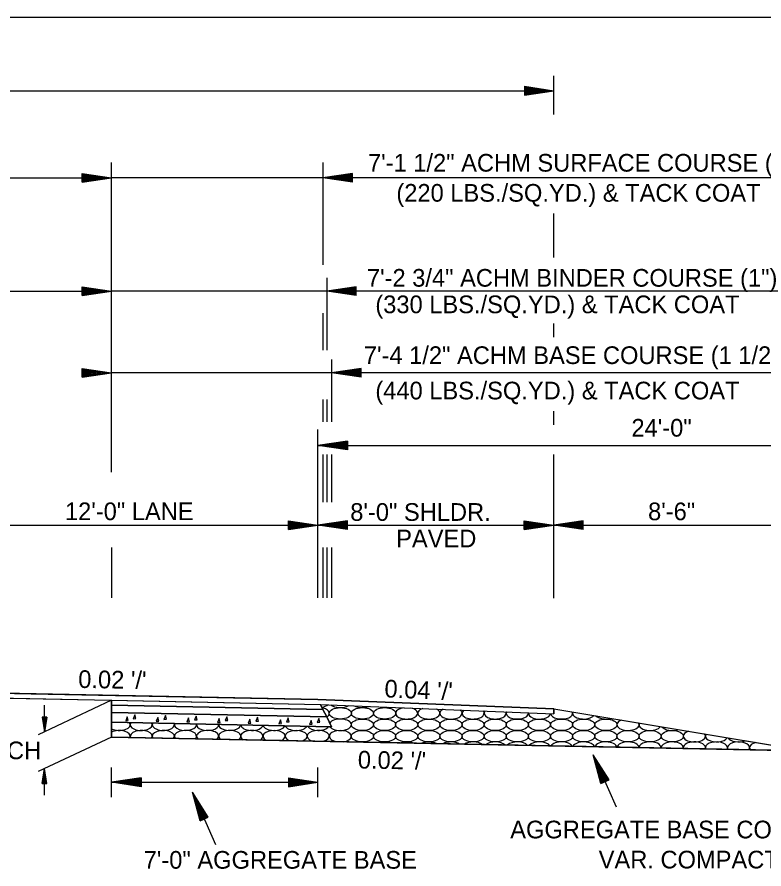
# Model space of a CAD drawing. Extents: x 1371763 to 1372860, y 385599 to 385872.
# Drawn here: x 1372091.19 to 1372116.52, y 385642.37 to 385671.28 of the extents above; entities that cross this region are included whole.
import ezdxf

# ---------------------------------------------------------------- set-up
doc = ezdxf.new("R2010")
doc.units = 0
doc.layers.add('R_Draft', color=7, linetype='Continuous')

msp = doc.modelspace()

# ---------------------------------------------------------------- linework, layer by layer
at = {"layer": 'R_Draft'}
for p, q in [((1372048.826, 385671.277), (1372117.962, 385671.277)), ((1372109.391, 385667.967), (1372109.391, 385669.287)), ((1372057.39, 385668.777), (1372109.391, 385668.777)), ((1372108.391, 385668.927), (1372109.391, 385668.777)), ((1372108.391, 385668.927), (1372108.391, 385668.627)), ((1372108.391, 385668.902), (1372109.224, 385668.777)), ((1372108.391, 385668.876), (1372109.052, 385668.777)), ((1372108.391, 385668.851), (1372108.885, 385668.777)), ((1372108.391, 385668.825), (1372108.716, 385668.777)), ((1372108.391, 385668.8), (1372108.549, 385668.777)), ((1372108.391, 385668.627), (1372109.391, 385668.777)), ((1372108.391, 385668.728), (1372108.716, 385668.777)), ((1372108.391, 385668.677), (1372109.052, 385668.777)), ((1372108.391, 385668.652), (1372109.224, 385668.777)), ((1372108.391, 385668.702), (1372108.885, 385668.777)), ((1372108.391, 385668.753), (1372108.549, 385668.777)), ((1372094.392, 385655.834), (1372094.393, 385666.343)), ((1372101.562, 385666.343), (1372101.562, 385662.864)), ((1372093.393, 385665.971), (1372094.393, 385665.821)), ((1372093.393, 385665.671), (1372093.393, 385665.971)), ((1372093.393, 385665.946), (1372094.226, 385665.821)), ((1372093.393, 385665.921), (1372094.054, 385665.821)), ((1372093.393, 385665.896), (1372093.888, 385665.821)), ((1372093.393, 385665.87), (1372093.718, 385665.821)), ((1372102.562, 385665.971), (1372101.562, 385665.821)), ((1372102.562, 385665.946), (1372101.729, 385665.821)), ((1372102.562, 385665.921), (1372101.901, 385665.821)), ((1372102.562, 385665.896), (1372102.067, 385665.821)), ((1372102.562, 385665.87), (1372102.237, 385665.821)), ((1372102.562, 385665.671), (1372102.562, 385665.971)), ((1372072.393, 385665.821), (1372094.393, 385665.821)), ((1372093.393, 385665.845), (1372093.551, 385665.821)), ((1372093.393, 385665.671), (1372094.393, 385665.821)), ((1372093.393, 385665.773), (1372093.718, 385665.821)), ((1372093.393, 385665.722), (1372094.054, 385665.821)), ((1372093.393, 385665.696), (1372094.226, 385665.821)), ((1372093.393, 385665.747), (1372093.888, 385665.821)), ((1372093.393, 385665.798), (1372093.551, 385665.821)), ((1372120.069, 385665.821), (1372094.393, 385665.821)), ((1372102.562, 385665.671), (1372101.562, 385665.821)), ((1372102.562, 385665.696), (1372101.729, 385665.821)), ((1372102.562, 385665.722), (1372101.901, 385665.821)), ((1372102.562, 385665.747), (1372102.067, 385665.821)), ((1372102.562, 385665.773), (1372102.237, 385665.821)), ((1372102.562, 385665.845), (1372102.404, 385665.821)), ((1372102.562, 385665.798), (1372102.404, 385665.821)), ((1372109.391, 385663.113), (1372109.391, 385664.613)), ((1372101.688, 385662.427), (1372101.688, 385659.975)), ((1372093.393, 385662.127), (1372094.393, 385661.977)), ((1372093.393, 385661.827), (1372093.393, 385662.127)), ((1372102.688, 385662.127), (1372101.688, 385661.977)), ((1372102.688, 385661.827), (1372102.688, 385662.127)), ((1372072.393, 385661.977), (1372094.393, 385661.977)), ((1372093.393, 385662.102), (1372094.226, 385661.977)), ((1372093.393, 385662.076), (1372094.054, 385661.977)), ((1372093.393, 385662.051), (1372093.888, 385661.977)), ((1372093.393, 385662.026), (1372093.718, 385661.977)), ((1372093.393, 385662), (1372093.551, 385661.977)), ((1372093.393, 385661.827), (1372094.393, 385661.977)), ((1372093.393, 385661.928), (1372093.718, 385661.977)), ((1372093.393, 385661.877), (1372094.054, 385661.977)), ((1372093.393, 385661.852), (1372094.226, 385661.977)), ((1372093.393, 385661.902), (1372093.888, 385661.977)), ((1372093.393, 385661.953), (1372093.551, 385661.977)), ((1372119.435, 385661.977), (1372094.393, 385661.977)), ((1372102.688, 385661.827), (1372101.688, 385661.977)), ((1372102.688, 385662.102), (1372101.855, 385661.977)), ((1372102.688, 385661.852), (1372101.855, 385661.977)), ((1372102.688, 385662.077), (1372102.027, 385661.977)), ((1372102.688, 385661.878), (1372102.027, 385661.977)), ((1372102.688, 385662.052), (1372102.193, 385661.977)), ((1372102.688, 385661.903), (1372102.193, 385661.977)), ((1372102.688, 385662.026), (1372102.363, 385661.977)), ((1372102.688, 385661.929), (1372102.363, 385661.977)), ((1372102.688, 385662.001), (1372102.53, 385661.977)), ((1372102.688, 385661.954), (1372102.53, 385661.977)), ((1372101.562, 385661.227), (1372101.562, 385659.975)), ((1372109.391, 385660.416), (1372109.391, 385660.881)), ((1372101.856, 385659.652), (1372101.856, 385657.536)), ((1372093.392, 385659.352), (1372094.392, 385659.202)), ((1372093.392, 385659.052), (1372093.392, 385659.352)), ((1372093.392, 385659.327), (1372094.225, 385659.202)), ((1372093.392, 385659.301), (1372094.053, 385659.202)), ((1372093.392, 385659.276), (1372093.887, 385659.202)), ((1372093.392, 385659.251), (1372093.717, 385659.202)), ((1372093.392, 385659.225), (1372093.55, 385659.202)), ((1372102.856, 385659.352), (1372101.856, 385659.202)), ((1372102.856, 385659.327), (1372102.023, 385659.202)), ((1372102.856, 385659.301), (1372102.195, 385659.202)), ((1372102.856, 385659.276), (1372102.362, 385659.202)), ((1372102.856, 385659.251), (1372102.531, 385659.202)), ((1372102.856, 385659.225), (1372102.698, 385659.202)), ((1372102.856, 385659.052), (1372102.856, 385659.352)), ((1372093.392, 385659.052), (1372094.392, 385659.202)), ((1372093.392, 385659.153), (1372093.717, 385659.202)), ((1372093.392, 385659.102), (1372094.053, 385659.202)), ((1372093.392, 385659.077), (1372094.225, 385659.202)), ((1372093.392, 385659.127), (1372093.887, 385659.202)), ((1372093.392, 385659.178), (1372093.55, 385659.202)), ((1372119.435, 385659.202), (1372094.393, 385659.202)), ((1372102.856, 385659.052), (1372101.856, 385659.202)), ((1372102.856, 385659.077), (1372102.023, 385659.202)), ((1372102.856, 385659.102), (1372102.195, 385659.202)), ((1372102.856, 385659.127), (1372102.362, 385659.202)), ((1372102.856, 385659.153), (1372102.531, 385659.202)), ((1372102.856, 385659.178), (1372102.698, 385659.202)), ((1372101.562, 385658.301), (1372101.562, 385657.536)), ((1372101.688, 385658.301), (1372101.688, 385657.536)), ((1372109.391, 385657.442), (1372109.391, 385657.908)), ((1372101.39, 385651.566), (1372101.391, 385657.279)), ((1372102.391, 385656.889), (1372101.391, 385656.739)), ((1372101.391, 385656.739), (1372125.391, 385656.739)), ((1372102.391, 385656.589), (1372101.391, 385656.739)), ((1372102.391, 385656.864), (1372101.558, 385656.739)), ((1372102.391, 385656.614), (1372101.558, 385656.739)), ((1372102.391, 385656.838), (1372101.73, 385656.739)), ((1372102.391, 385656.639), (1372101.73, 385656.739)), ((1372102.391, 385656.813), (1372101.896, 385656.739)), ((1372102.391, 385656.664), (1372101.896, 385656.739)), ((1372102.391, 385656.787), (1372102.066, 385656.739)), ((1372102.391, 385656.69), (1372102.066, 385656.739)), ((1372102.391, 385656.762), (1372102.233, 385656.739)), ((1372102.391, 385656.715), (1372102.233, 385656.739)), ((1372102.391, 385656.889), (1372102.391, 385656.589)), ((1372101.562, 385656.428), (1372101.562, 385654.819)), ((1372101.688, 385656.428), (1372101.688, 385654.819)), ((1372101.856, 385656.428), (1372101.856, 385654.819)), ((1372109.39, 385651.56), (1372109.391, 385656.427)), ((1372089.39, 385654.032), (1372101.39, 385654.032)), ((1372100.39, 385654.182), (1372101.39, 385654.032)), ((1372100.39, 385653.882), (1372100.39, 385654.182)), ((1372100.39, 385654.157), (1372101.223, 385654.032)), ((1372100.39, 385654.132), (1372101.051, 385654.032)), ((1372100.39, 385654.107), (1372100.885, 385654.032)), ((1372100.39, 385654.081), (1372100.715, 385654.032)), ((1372100.39, 385654.056), (1372100.548, 385654.032)), ((1372100.39, 385653.882), (1372101.39, 385654.032)), ((1372100.39, 385653.984), (1372100.715, 385654.032)), ((1372100.39, 385653.933), (1372101.051, 385654.032)), ((1372100.39, 385653.907), (1372101.223, 385654.032)), ((1372100.39, 385653.958), (1372100.885, 385654.032)), ((1372100.39, 385654.009), (1372100.548, 385654.032)), ((1372102.39, 385654.182), (1372101.39, 385654.032)), ((1372102.39, 385653.882), (1372101.39, 385654.032)), ((1372101.39, 385654.032), (1372109.39, 385654.032)), ((1372102.39, 385654.157), (1372101.557, 385654.032)), ((1372102.39, 385653.907), (1372101.557, 385654.032)), ((1372102.39, 385654.132), (1372101.729, 385654.032)), ((1372102.39, 385653.933), (1372101.729, 385654.032)), ((1372102.39, 385654.107), (1372101.896, 385654.032)), ((1372102.39, 385653.958), (1372101.896, 385654.032)), ((1372102.39, 385654.081), (1372102.065, 385654.032)), ((1372102.39, 385653.984), (1372102.065, 385654.032)), ((1372102.39, 385654.056), (1372102.232, 385654.032)), ((1372102.39, 385654.009), (1372102.232, 385654.032)), ((1372102.39, 385653.882), (1372102.39, 385654.182)), ((1372108.39, 385654.182), (1372109.39, 385654.032)), ((1372108.39, 385653.882), (1372108.39, 385654.182)), ((1372108.39, 385654.157), (1372109.223, 385654.032)), ((1372108.39, 385654.132), (1372109.051, 385654.032)), ((1372108.39, 385654.107), (1372108.885, 385654.032)), ((1372108.39, 385654.081), (1372108.715, 385654.032)), ((1372108.39, 385654.056), (1372108.548, 385654.032)), ((1372108.39, 385653.882), (1372109.39, 385654.032)), ((1372108.39, 385653.984), (1372108.715, 385654.032)), ((1372108.39, 385653.933), (1372109.051, 385654.032)), ((1372108.39, 385653.907), (1372109.223, 385654.032)), ((1372108.39, 385653.958), (1372108.885, 385654.032)), ((1372108.39, 385654.009), (1372108.548, 385654.032)), ((1372110.39, 385654.182), (1372109.39, 385654.032)), ((1372110.39, 385653.882), (1372109.39, 385654.032)), ((1372109.39, 385654.032), (1372117.962, 385654.031)), ((1372110.39, 385654.157), (1372109.557, 385654.032)), ((1372110.39, 385653.907), (1372109.557, 385654.032)), ((1372110.39, 385654.132), (1372109.729, 385654.032)), ((1372110.39, 385653.933), (1372109.729, 385654.032)), ((1372110.39, 385654.107), (1372109.896, 385654.032)), ((1372110.39, 385653.958), (1372109.896, 385654.032)), ((1372110.39, 385654.081), (1372110.065, 385654.032)), ((1372110.39, 385653.984), (1372110.065, 385654.032)), ((1372110.39, 385654.056), (1372110.232, 385654.032)), ((1372110.39, 385654.009), (1372110.232, 385654.032)), ((1372110.39, 385653.882), (1372110.39, 385654.182)), ((1372094.392, 385653.282), (1372094.392, 385651.566)), ((1372101.562, 385653.282), (1372101.562, 385651.566)), ((1372101.688, 385653.282), (1372101.688, 385651.566)), ((1372101.856, 385653.282), (1372101.856, 385651.566)), ((1372083.393, 385648.481), (1372101.393, 385648.121)), ((1372083.393, 385648.314), (1372101.477, 385647.952)), ((1372094.392, 385648.094), (1372091.905, 385646.922)), ((1372101.393, 385648.121), (1372109.393, 385647.801)), ((1372101.477, 385647.952), (1372101.562, 385647.784)), ((1372101.477, 385647.952), (1372109.393, 385647.636)), ((1372092.117, 385647.022), (1372092.117, 385647.922)), ((1372094.393, 385647.677), (1372101.688, 385647.531)), ((1372101.562, 385647.784), (1372101.688, 385647.531)), ((1372109.393, 385647.801), (1372125.393, 385645.134)), ((1372109.393, 385647.801), (1372109.393, 385647.636)), ((1372092.042, 385647.522), (1372092.117, 385647.022)), ((1372092.192, 385647.522), (1372092.042, 385647.522)), ((1372092.055, 385647.522), (1372092.117, 385647.106)), ((1372092.068, 385647.522), (1372092.117, 385647.192)), ((1372092.08, 385647.522), (1372092.117, 385647.275)), ((1372092.093, 385647.522), (1372092.117, 385647.36)), ((1372092.106, 385647.522), (1372092.117, 385647.443)), ((1372092.192, 385647.522), (1372092.117, 385647.022)), ((1372092.142, 385647.522), (1372092.117, 385647.36)), ((1372092.167, 385647.522), (1372092.117, 385647.192)), ((1372092.18, 385647.522), (1372092.117, 385647.106)), ((1372092.155, 385647.522), (1372092.117, 385647.275)), ((1372092.129, 385647.522), (1372092.117, 385647.443)), ((1372101.688, 385647.531), (1372101.856, 385647.195)), ((1372094.393, 385647.344), (1372101.856, 385647.195)), ((1372094.393, 385646.844), (1372091.905, 385645.672)), ((1372094.393, 385646.844), (1372117.962, 385646.373)), ((1372110.989, 385645.27), (1372110.724, 385646.246)), ((1372111.263, 385645.39), (1372110.724, 385646.246)), ((1372110.724, 385646.246), (1372111.503, 385644.472)), ((1372111.012, 385645.28), (1372110.791, 385646.093)), ((1372111.24, 385645.38), (1372110.791, 385646.093)), ((1372111.217, 385645.37), (1372110.86, 385645.935)), ((1372111.035, 385645.29), (1372110.86, 385645.935)), ((1372092.043, 385645.272), (1372092.118, 385645.772)), ((1372092.055, 385645.272), (1372092.118, 385645.689)), ((1372092.193, 385645.272), (1372092.118, 385645.772)), ((1372092.118, 385644.872), (1372092.118, 385645.772)), ((1372092.18, 385645.272), (1372092.118, 385645.689)), ((1372094.393, 385644.809), (1372094.393, 385645.809)), ((1372101.39, 385644.809), (1372101.39, 385645.809)), ((1372111.058, 385645.3), (1372110.927, 385645.783)), ((1372111.194, 385645.36), (1372110.927, 385645.783)), ((1372092.068, 385645.272), (1372092.118, 385645.603)), ((1372092.081, 385645.272), (1372092.118, 385645.52)), ((1372092.094, 385645.272), (1372092.118, 385645.435)), ((1372092.106, 385645.272), (1372092.118, 385645.351)), ((1372092.168, 385645.272), (1372092.118, 385645.603)), ((1372092.155, 385645.272), (1372092.118, 385645.52)), ((1372092.142, 385645.272), (1372092.118, 385645.435)), ((1372092.13, 385645.272), (1372092.118, 385645.351)), ((1372095.393, 385645.459), (1372094.393, 385645.309)), ((1372095.393, 385645.434), (1372094.56, 385645.309)), ((1372095.393, 385645.409), (1372094.732, 385645.309)), ((1372095.393, 385645.384), (1372094.899, 385645.309)), ((1372095.393, 385645.358), (1372095.068, 385645.309)), ((1372095.393, 385645.459), (1372095.393, 385645.159)), ((1372100.39, 385645.459), (1372101.39, 385645.309)), ((1372100.39, 385645.459), (1372100.39, 385645.159)), ((1372100.39, 385645.434), (1372101.223, 385645.309)), ((1372100.39, 385645.409), (1372101.051, 385645.309)), ((1372100.39, 385645.384), (1372100.884, 385645.309)), ((1372100.39, 385645.358), (1372100.715, 385645.309)), ((1372110.989, 385645.27), (1372111.263, 385645.39)), ((1372111.171, 385645.35), (1372110.995, 385645.628)), ((1372111.082, 385645.311), (1372110.995, 385645.628)), ((1372111.148, 385645.339), (1372111.062, 385645.475)), ((1372111.104, 385645.321), (1372111.062, 385645.475)), ((1372092.043, 385645.272), (1372092.193, 385645.272)), ((1372095.393, 385645.159), (1372094.393, 385645.309)), ((1372094.393, 385645.309), (1372101.39, 385645.309)), ((1372095.393, 385645.184), (1372094.56, 385645.309)), ((1372095.393, 385645.21), (1372094.732, 385645.309)), ((1372095.393, 385645.235), (1372094.899, 385645.309)), ((1372095.393, 385645.26), (1372095.068, 385645.309)), ((1372095.393, 385645.333), (1372095.235, 385645.309)), ((1372095.393, 385645.286), (1372095.235, 385645.309)), ((1372100.39, 385645.333), (1372100.548, 385645.309)), ((1372100.39, 385645.159), (1372101.39, 385645.309)), ((1372100.39, 385645.26), (1372100.715, 385645.309)), ((1372100.39, 385645.21), (1372101.051, 385645.309)), ((1372100.39, 385645.184), (1372101.223, 385645.309)), ((1372100.39, 385645.235), (1372100.884, 385645.309)), ((1372100.39, 385645.286), (1372100.548, 385645.309)), ((1372097.399, 385644.001), (1372097.134, 385644.977)), ((1372097.674, 385644.121), (1372097.134, 385644.977)), ((1372097.134, 385644.977), (1372097.913, 385643.203)), ((1372097.422, 385644.011), (1372097.201, 385644.824)), ((1372097.651, 385644.111), (1372097.201, 385644.824)), ((1372097.627, 385644.101), (1372097.27, 385644.666)), ((1372097.445, 385644.021), (1372097.27, 385644.666)), ((1372097.468, 385644.031), (1372097.337, 385644.514)), ((1372097.604, 385644.091), (1372097.337, 385644.514)), ((1372097.581, 385644.081), (1372097.406, 385644.359)), ((1372097.492, 385644.042), (1372097.406, 385644.359)), ((1372097.558, 385644.07), (1372097.473, 385644.206)), ((1372097.515, 385644.052), (1372097.473, 385644.206)), ((1372097.399, 385644.001), (1372097.674, 385644.121))]:
    msp.add_line(p, q, dxfattribs=at)
for points in [[(1372083.393, 385648.481), (1372065.393, 385648.121), (1372057.393, 385647.801), (1372057.393, 385647.636), (1372065.309, 385647.952), (1372072.394, 385648.094), (1372083.393, 385648.314), (1372094.392, 385648.094), (1372101.477, 385647.952), (1372109.393, 385647.636), (1372109.393, 385647.801), (1372101.393, 385648.121)], [(1372094.392, 385648.094), (1372101.477, 385647.952), (1372101.562, 385647.784), (1372094.393, 385647.927)], [(1372094.393, 385646.844), (1372094.393, 385647.344), (1372101.856, 385647.195), (1372101.688, 385647.531), (1372101.562, 385647.784), (1372101.477, 385647.952), (1372109.393, 385647.636), (1372109.393, 385647.801), (1372117.962, 385646.373)], [(1372094.393, 385647.677), (1372094.393, 385647.927), (1372101.562, 385647.784), (1372101.688, 385647.531)], [(1372094.393, 385647.677), (1372101.688, 385647.531), (1372101.856, 385647.195), (1372094.393, 385647.344)]]:
    msp.add_lwpolyline(points, close=True, dxfattribs=at)
for points in [[(1372094.392, 385648.094), (1372094.393, 385647.927), (1372094.393, 385647.677), (1372094.393, 385647.344), (1372094.393, 385646.844)], [(1372094.393, 385647.927), (1372101.562, 385647.784)], [(1372094.919, 385647.533), (1372094.871, 385647.4), (1372094.959, 385647.404), (1372094.919, 385647.533)], [(1372095.178, 385647.599), (1372095.13, 385647.466), (1372095.218, 385647.47), (1372095.178, 385647.599)], [(1372095.959, 385647.512), (1372095.91, 385647.379), (1372095.998, 385647.383), (1372095.959, 385647.512)], [(1372096.218, 385647.578), (1372096.169, 385647.445), (1372096.257, 385647.449), (1372096.218, 385647.578)], [(1372096.999, 385647.491), (1372096.95, 385647.358), (1372097.038, 385647.362), (1372096.999, 385647.491)], [(1372097.258, 385647.557), (1372097.209, 385647.424), (1372097.297, 385647.428), (1372097.258, 385647.557)], [(1372098.039, 385647.47), (1372097.99, 385647.338), (1372098.078, 385647.341), (1372098.039, 385647.47)], [(1372098.298, 385647.536), (1372098.249, 385647.404), (1372098.337, 385647.407), (1372098.298, 385647.536)], [(1372099.078, 385647.45), (1372099.03, 385647.317), (1372099.118, 385647.32), (1372099.078, 385647.45)], [(1372099.337, 385647.516), (1372099.289, 385647.383), (1372099.377, 385647.386), (1372099.337, 385647.516)], [(1372100.118, 385647.429), (1372100.07, 385647.296), (1372100.158, 385647.3), (1372100.118, 385647.429)], [(1372100.377, 385647.495), (1372100.329, 385647.362), (1372100.417, 385647.366), (1372100.377, 385647.495)], [(1372101.158, 385647.408), (1372101.11, 385647.275), (1372101.198, 385647.279), (1372101.158, 385647.408)], [(1372101.417, 385647.474), (1372101.369, 385647.341), (1372101.457, 385647.345), (1372101.417, 385647.474)]]:
    msp.add_lwpolyline(points, dxfattribs=at)
for centre, start_param, end_param in [((1372101.401, 385648.039), 5.051096, 5.763875), ((1372101.401, 385647.65), 0.74402, 1.197348), ((1372101.401, 385647.65), 5.592596, 7.027205), ((1372102.151, 385648.039), 3.685644, 5.585033), ((1372102.902, 385648.039), 3.891507, 5.37917), ((1372103.652, 385648.039), 4.161511, 5.109166), ((1372104.402, 385647.65), 1.810379, 6.670932), ((1372104.402, 385647.65), 0.387746, 1.177112), ((1372105.153, 385647.65), 2.143322, 6.592146), ((1372105.153, 385647.65), 0.308961, 0.84417), ((1372105.903, 385647.65), 2.366927, 6.51554), ((1372105.903, 385647.65), 0.232354, 0.620564), ((1372106.653, 385647.65), 2.554238, 6.44052), ((1372106.653, 385647.65), 0.157335, 0.433254), ((1372107.403, 385647.65), 2.723473, 6.366593), ((1372108.154, 385647.65), 2.883001, 6.293319), ((1372107.403, 385647.65), 0.083407, 0.264018), ((1372108.904, 385647.65), 3.037942, 6.232735), ((1372108.154, 385647.65), 0.010134, 0.104491), ((1372109.654, 385647.65), 3.19224, 6.523589), ((1372109.654, 385647.65), 2.278485, 2.33986), ((1372110.404, 385647.65), 2.918865, 5.883208), ((1372102.151, 385647.262), 3.48684, 9.119957), ((1372111.155, 385647.65), 3.607321, 5.194752), ((1372111.905, 385647.262), 2.199247, 6.602826), ((1372094.649, 385647.262), 3.96261, 6.65316), ((1372094.649, 385646.873), 6.067704, 8.604148), ((1372095.399, 385647.262), 2.777136, 6.570444), ((1372095.399, 385646.873), 5.988661, 9.642104), ((1372096.149, 385646.873), 5.907944, 9.722821), ((1372096.149, 385647.262), 2.857595, 6.489984), ((1372096.9, 385646.873), 5.824873, 9.805892), ((1372096.9, 385647.262), 2.936461, 6.411118), ((1372097.65, 385646.873), 5.738592, 9.892174), ((1372097.65, 385647.262), 3.014293, 6.333287), ((1372098.4, 385646.873), 5.647958, 9.982807), ((1372098.4, 385647.262), 3.091588, 6.255992), ((1372099.15, 385646.873), 5.551342, 10.079423), ((1372099.15, 385647.262), 3.168815, 6.178765), ((1372099.901, 385647.262), 3.246438, 6.101142), ((1372100.651, 385647.262), 3.324943, 6.022637), ((1372101.401, 385647.262), 3.404868, 5.942711), ((1372102.151, 385646.873), 4.998472, 8.461578), ((1372112.655, 385647.262), 2.852988, 5.949086), ((1372113.406, 385647.262), 3.518815, 5.283258), ((1372099.901, 385646.873), 5.446223, 10.184542), ((1372100.651, 385646.873), 5.328222, 10.302543), ((1372101.401, 385646.873), 5.188221, 10.442545), ((1372102.151, 385646.873), 2.178393, 4.349107), ((1372114.156, 385646.873), 2.115117, 6.31057), ((1372114.156, 385646.873), 0.027385, 0.403771), ((1372114.906, 385646.873), 2.787209, 6.014865), ((1372115.656, 385646.873), 3.436349, 5.365724), ((1372102.902, 385646.485), 1.301815, 1.762579), ((1372103.652, 385646.485), 1.072981, 1.991414), ((1372104.402, 385646.485), 0.921452, 2.142942), ((1372105.153, 385646.485), 0.797512, 2.266882), ((1372105.903, 385646.485), 0.688711, 2.375683), ((1372106.653, 385646.485), 0.589594, 2.4748), ((1372107.403, 385646.485), 0.497173, 2.567222), ((1372108.154, 385646.485), 0.409581, 2.654814), ((1372108.904, 385646.485), 0.325542, 2.738853), ((1372109.654, 385646.485), 0.24412, 2.820275), ((1372110.404, 385646.485), 0.164585, 2.89981), ((1372111.155, 385646.485), 0.086335, 2.978059), ((1372111.905, 385646.485), 0.008849, 3.055545), ((1372112.655, 385646.485), 0.853185, 3.132747), ((1372112.655, 385646.485), 6.214833, 7.136371), ((1372113.406, 385646.485), 0.568033, 3.210126), ((1372113.406, 385646.485), 6.137454, 6.851218), ((1372114.156, 385646.485), 0.337275, 3.288156), ((1372114.906, 385646.485), 0.129417, 3.367348), ((1372114.156, 385646.485), 6.059423, 6.620461), ((1372114.906, 385646.485), 5.980232, 6.412602), ((1372115.656, 385646.485), 3.013817, 3.448278), ((1372115.656, 385646.485), 5.899301, 9.297002), ((1372116.407, 385646.485), 2.024311, 3.531644)]:
    msp.add_ellipse(centre, major_axis=(0.375, 0), ratio=0.517889, start_param=start_param, end_param=end_param, dxfattribs=at)
for centre in [(1372102.151, 385647.65), (1372102.902, 385647.65), (1372103.652, 385647.65), (1372102.902, 385647.262), (1372103.652, 385647.262), (1372104.402, 385647.262), (1372105.153, 385647.262), (1372105.903, 385647.262), (1372106.653, 385647.262), (1372107.403, 385647.262), (1372108.154, 385647.262), (1372108.904, 385647.262), (1372109.654, 385647.262), (1372110.404, 385647.262), (1372111.155, 385647.262), (1372102.902, 385646.873), (1372103.652, 385646.873), (1372104.402, 385646.873), (1372105.153, 385646.873), (1372105.903, 385646.873), (1372106.653, 385646.873), (1372107.403, 385646.873), (1372108.154, 385646.873), (1372108.904, 385646.873), (1372109.654, 385646.873), (1372110.404, 385646.873), (1372111.155, 385646.873), (1372111.905, 385646.873), (1372112.655, 385646.873), (1372113.406, 385646.873)]:
    msp.add_ellipse(centre, major_axis=(0.375, 0), ratio=0.517889, dxfattribs=at)

# ---------------------------------------------------------------- texts
for s, rotation, p in [('7\'-1 1/2" ACHM SURFACE COURSE (1/2")', 0, (1372103.089, 385666.031)), ('(220 LBS./SQ.YD.) & TACK COAT', 0, (1372104.051, 385665.011)), ('7\'-2 3/4" ACHM BINDER COURSE (1")', 0, (1372103.053, 385662.127)), ('(330 LBS./SQ.YD.) & TACK COAT', 0, (1372103.338, 385661.227)), ('7\'-4 1/2" ACHM BASE COURSE (1 1/2")', 360, (1372102.949, 385659.502)), ('(440 LBS./SQ.YD.) & TACK COAT', 360, (1372103.338, 385658.302)), ('12\'-0" LANE', 360, (1372092.812, 385654.204)), ('8\'-0" SHLDR.', 360, (1372102.487, 385654.181)), ('8\'-6"', 360, (1372112.587, 385654.202)), ('PAVED', 360, (1372104.044, 385653.281)), ("0.02 '/'", 359.0147, (1372093.259, 385648.513)), ("0.04 '/'", 357.6223, (1372103.637, 385648.193)), ("0.02 '/'", 359.0147, (1372102.74, 385645.778)), ('AGGREGATE BASE COURSE (CLASS 7)', 360, (1372107.912, 385643.406)), ('7\'-0" AGGREGATE BASE ', 360, (1372095.482, 385642.377)), ('VAR. COMPACTED DEPTH', 360, (1372110.912, 385642.386))]:
    msp.add_text(s, height=0.6, rotation=rotation, dxfattribs=at).set_placement(p)
for s, p in [('24\'-0"', (1372112.023, 385657.039)), ('15" NOTCH', (1372087.751, 385646.091))]:
    msp.add_text(s, height=0.6, dxfattribs=at).set_placement(p)

doc.saveas('drawing.dxf')
